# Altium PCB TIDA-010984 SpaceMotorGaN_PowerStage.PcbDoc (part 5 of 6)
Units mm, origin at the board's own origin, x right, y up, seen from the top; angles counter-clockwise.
Board outline 177.8 x 152.4 mm, 8 copper layers (Top Layer, DC LINK Layer 2, GND Layer 3, 3V3 Layer 4, Layer 5, Layer 6, GND Layer 7, Bottom Layer), stack 1.554 mm thick; 582 components, 280 nets, 1847 pads, 979 vias.
Unrouted connection lines stored in the file: 474.
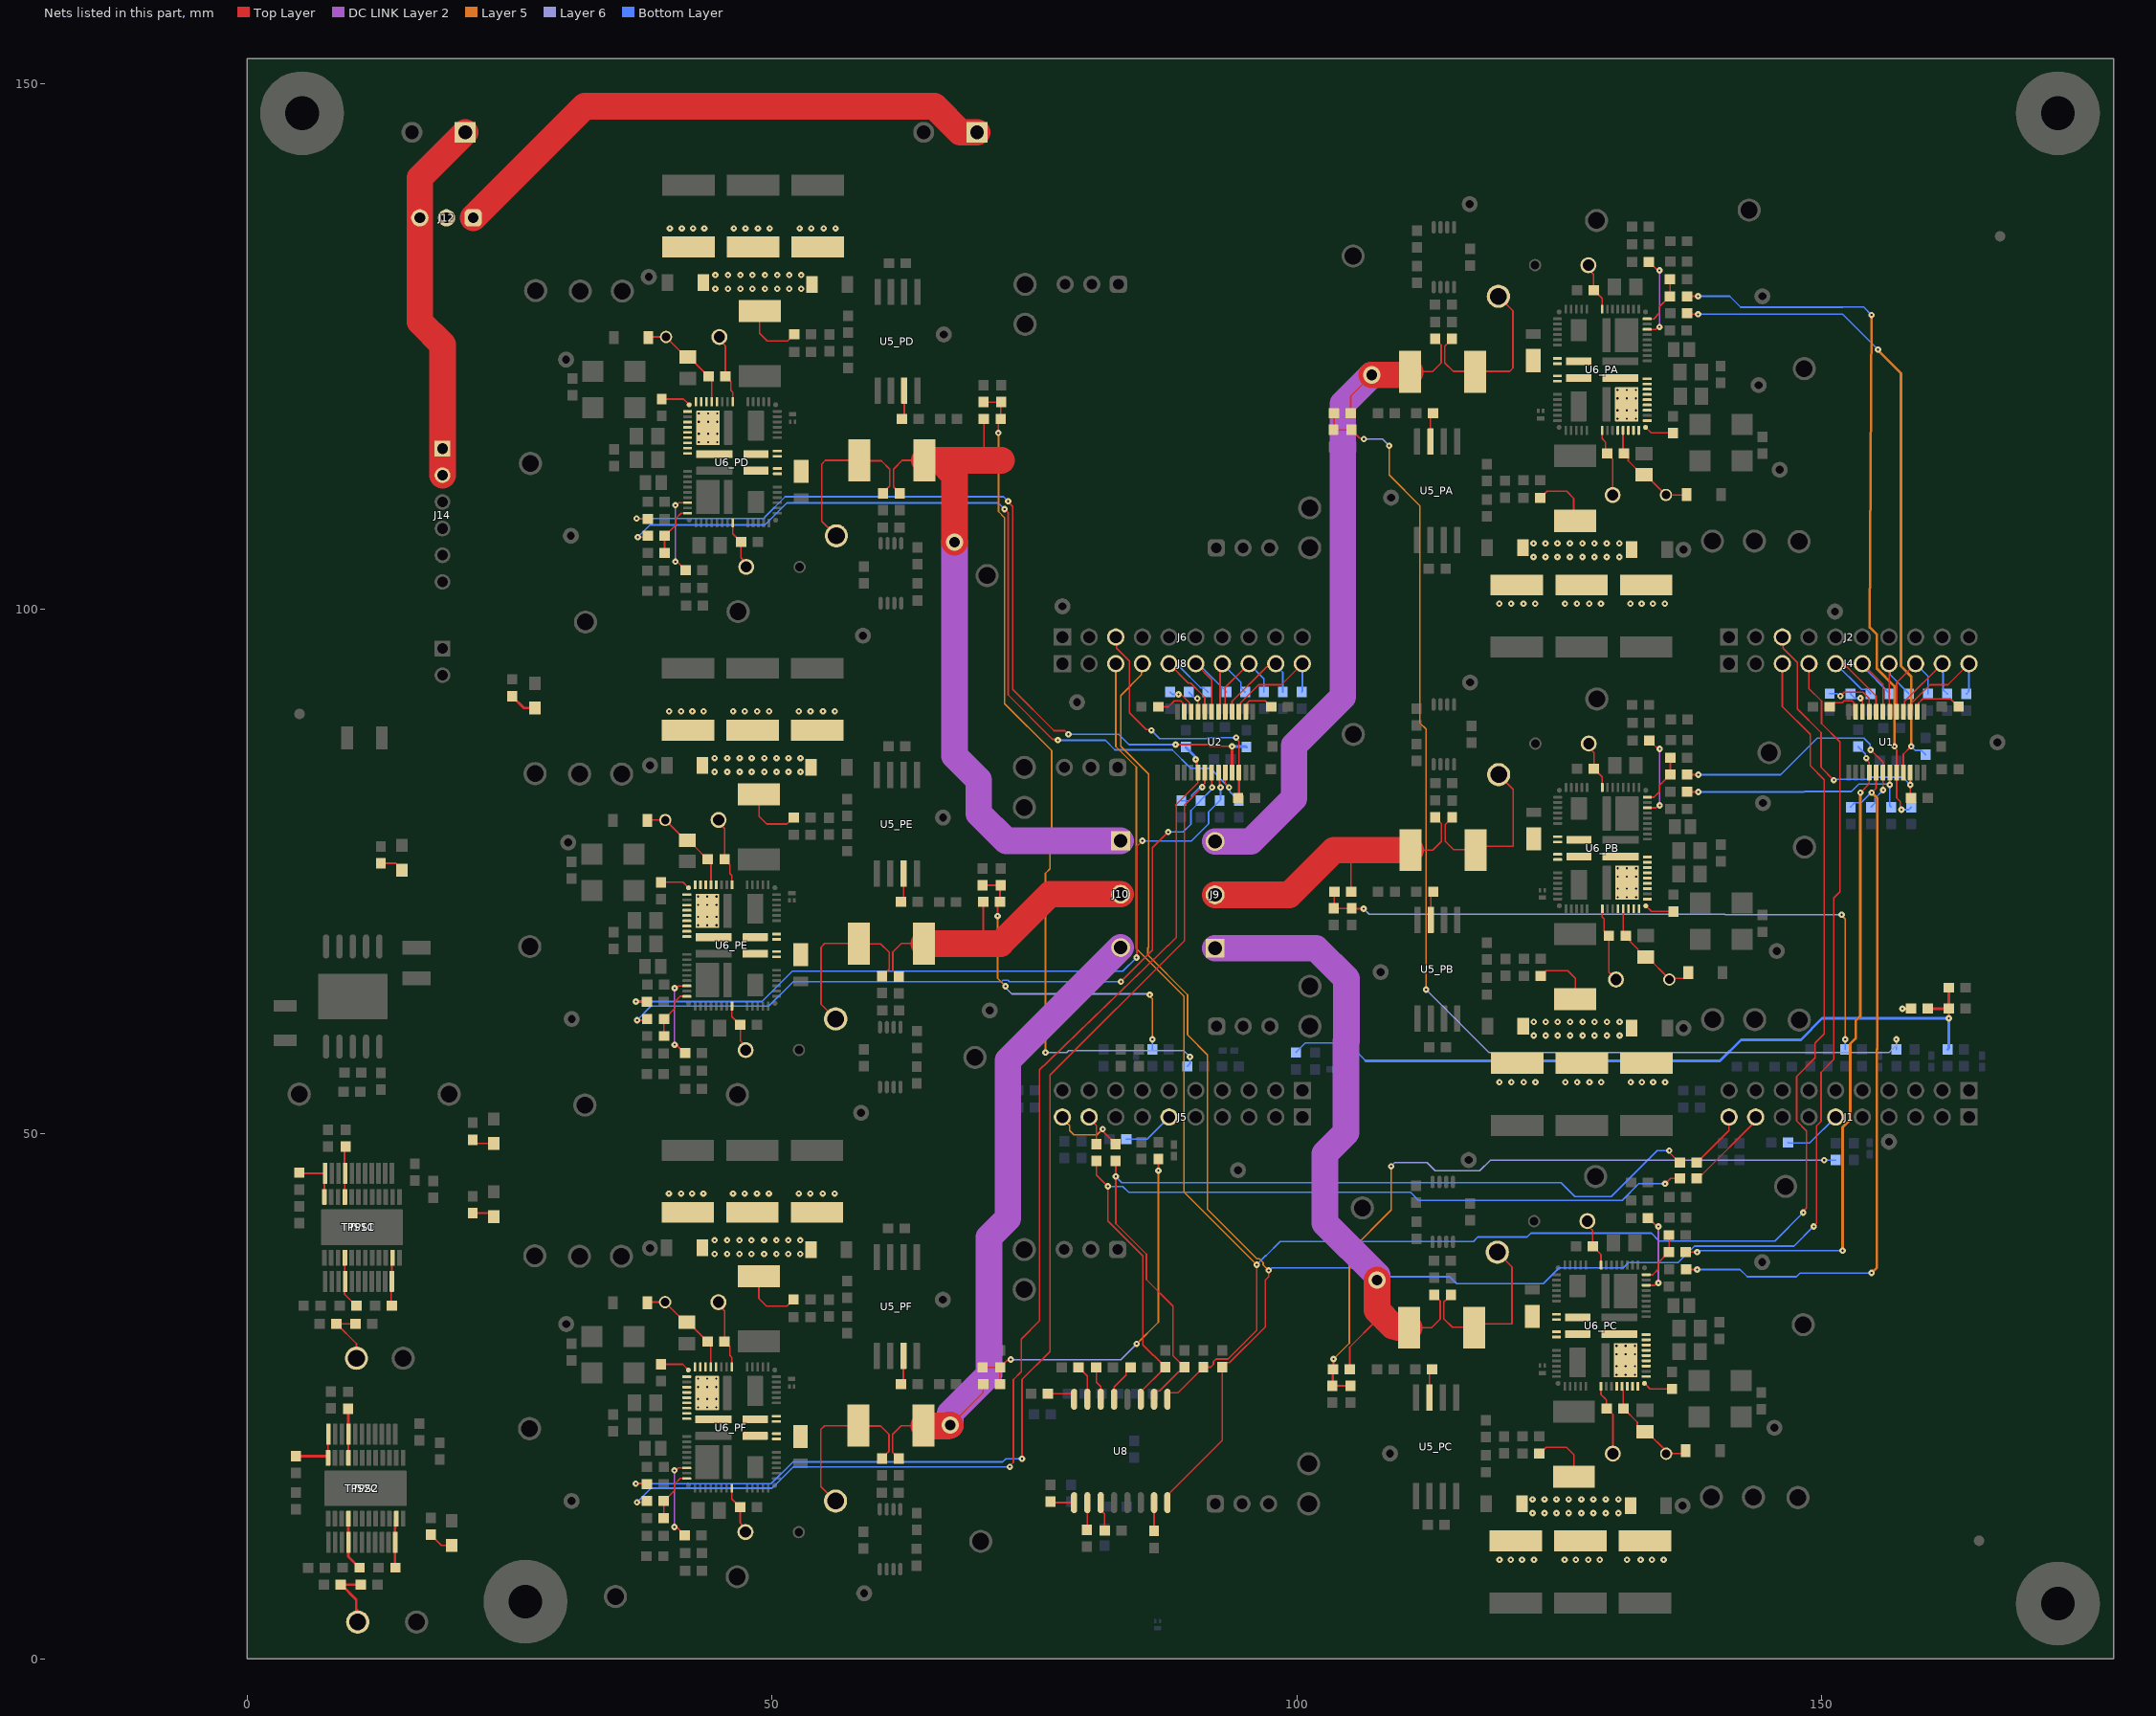
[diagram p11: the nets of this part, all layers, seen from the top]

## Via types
v1: diameter 0.61, hole 0.2, Top Layer to Bottom Layer, tented both sides, 306 vias
v2: diameter 0.61, hole 0.203, Top Layer to Bottom Layer, tented both sides, 272 vias
v3: diameter 0.5, hole 0.2, Top Layer to Bottom Layer, tented both sides, 216 vias
v4: diameter 0.5, hole 0.2, Top Layer to Bottom Layer, 66 vias
v5: diameter 0.61, hole 0.2, Top Layer to Bottom Layer, 61 vias
v6: diameter 0.864, hole 0.406, Top Layer to Bottom Layer, tented both sides, 17 vias
v7: diameter 1.651, hole 1.016, Top Layer to Bottom Layer, tented both sides, 12 vias
v8: diameter 0.864, hole 0.406, Top Layer to Bottom Layer, 9 vias
v9: diameter 0.61, hole 0.203, Top Layer to Bottom Layer, 8 vias
v10: diameter 1.27, hole 0.711, Top Layer to Bottom Layer, tented both sides, 5 vias
v11: diameter 0.61, hole 0.2, Top Layer to Bottom Layer, tented top, 2 vias
v12: diameter 1.651, hole 1.016, Top Layer to Bottom Layer, 2 vias
v13: diameter 0.61, hole 0.203, Top Layer to Bottom Layer, tented bottom, 1 vias
v14: diameter 1.27, hole 0.711, Top Layer to Bottom Layer, 1 vias
v15: diameter 1.651, hole 1.016, Top Layer to Bottom Layer, tented top, 1 vias

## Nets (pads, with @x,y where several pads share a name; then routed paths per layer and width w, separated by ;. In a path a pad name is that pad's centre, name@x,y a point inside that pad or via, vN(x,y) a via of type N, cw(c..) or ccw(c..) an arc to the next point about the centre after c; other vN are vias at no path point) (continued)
NetD10_1: D10.1 R102.1 | length 2.3
  Top Layer w0.152: R102.1@12.75,75.769 14.178,75.769 14.75,75.197 D10.1@14.75,75.122
NetD12_1: D12.1 R110.1 | length 2.6
  Top Layer w0.254: R110.1@25.25,91.675 26.362,90.563 D12.1@27.432,90.563
NetD13_1: D13.1 R111.1 | length 2.1
  Top Layer w0.152: R111.1@21.5,42.45 23.173,42.45 D13.1@23.5,42.123
NetD14_1: D14.1 R112.1 | length 2.4
  Top Layer w0.152: R112.1@17.5,11.84 17.5,11.815 18.511,10.804 D14.1@19.5,10.804
NetD17_1: D17.1 R114.1 | length 2.2
  Top Layer w0.152: R114.1@21.5,49.45 21.875,49.075 D17.1@23.5,49.075
NetJ1_6: J1.6 R14.2 | length 5.6
  Bottom Layer w0.152: R14.2@146.8,49.169 146.849,49.12 148.853,49.12 J1.6@151.336,51.602
NetJ1_9: J1.9 R115.2 | length 8.3
  Top Layer w0.152: R115.2@138.107,45.75 138.506,46.149 138.644,46.149 143.716,51.22 J1.9@143.716,51.602
NetJ1_10: J1.10 R116.2 | length 5.6
  Top Layer w0.152: R116.2@138.096,47.25 138.121,47.25 139.169,48.298 139.169,48.317 141.176,50.323 J1.10@141.176,51.602
NetJ2_3: J2.3 R8.1 U1.22 | length 25.9
  Top Layer w0.152: J2.3@146.256,97.322 146.327,97.252 146.327,96.269 147.695,94.901 147.695,90.474 149.944,88.225 149.944,84.915 v1(151.167,83.692) ; U1.22@158.441,84.416 v1(158.441,83.25) 158.441,82.075 R8.1@158.516,82
  Bottom Layer w0.152: J2.3@146.256,97.322 J2.3@146.327,97.252 ; v1(151.167,83.692) 151.247,83.773 154.438,83.773 154.644,83.979 157.711,83.979 v1(158.441,83.25)
NetJ4_5: J4.5 R19.2 U1.8 | length 11.2
  Top Layer w0.152: J4.5@151.336,94.782 151.606,94.512 152.389,94.512 155.191,91.71 U1.8@155.191,90.216
  Bottom Layer w0.152: J4.5@151.336,94.782 153.785,92.333 154.274,92.333 154.673,91.934 R19.2@154.673,91.909
NetJ4_6: J4.6 R18.2 U1.7 | length 9.3
  Top Layer w0.152: J4.6@153.876,94.782 155.841,92.817 U1.7@155.841,90.216
  Bottom Layer w0.152: J4.6@153.876,94.782 153.876,94.556 156.498,91.934 R18.2@156.498,91.909
NetJ4_7: J4.7 R17.2 U1.6 | length 8.3
  Top Layer w0.152: J4.7@156.416,94.782 156.453,94.745 156.453,90.253 U1.6@156.491,90.216
  Bottom Layer w0.152: J4.7@156.416,94.782 156.528,94.67 156.528,93.729 158.323,91.934 R17.2@158.323,91.909
NetJ4_8: J4.8 R16.2 U1.5 | length 8.7
  Top Layer w0.152: U1.5@157.141,90.216 157.141,92.967 J4.8@158.956,94.782
  Bottom Layer w0.152: J4.8@158.956,94.782 160.148,93.591 R16.2@160.148,91.909
NetJ4_9: J4.9 R15.2 U1.4 | length 9.2
  Top Layer w0.152: U1.4@157.791,90.216 157.908,90.333 157.908,91.194 J4.9@161.496,94.782
  Bottom Layer w0.152: J4.9@161.496,94.782 161.573,94.705 161.573,92.308 R15.2@161.972,91.909
NetJ4_10: J4.10 R13.2 U1.3 | length 10.9
  Top Layer w0.152: U1.3@158.441,90.216 158.589,90.365 158.589,91.051 160.312,92.774 162.027,92.774 J4.10@164.036,94.782
  Bottom Layer w0.152: R13.2@163.797,91.909 164.036,92.148 J4.10@164.036,94.782
NetJ5_6: J5.6 R113.2 | length 5
  Bottom Layer w0.152: R113.2@83.75,49.5 85.733,49.5 J5.6@87.836,51.602
NetJ5_9: J5.9 R117.2 | length 2.9
  Top Layer w0.152: J5.9@80.216,51.602 80.216,51.495 80.907,50.804 R117.2@80.907,49.02
NetJ5_10: J5.10 R118.2 | length 7.1
  Top Layer w0.152: v1(81.517,50.462) 81.517,50.392 81.605,50.304 81.605,50.196 82.756,49.045 R118.2@82.756,49.02
  Layer 5 w0.152: J5.10@77.676,51.602 77.676,51.483 78.361,50.798 78.361,50.318 78.759,49.919 80.974,49.919 v1(81.517,50.462)
NetJ6_3: J6.3 R35.1 U2.22 | length 24.8
  Top Layer w0.152: J6.3@82.756,97.322 82.827,97.252 82.827,96.269 84.049,95.047 84.049,90.12 85.646,88.522 86.066,88.522 v1(86.154,88.435) ; v1(94.227,87.753) 94.227,87.629 94.491,87.365 U2.22@94.491,84.416
  Top Layer w0.254: R35.1@94.491,82.085 U2.22@94.491,84.416
  Bottom Layer w0.152: v1(86.154,88.435) 86.93,87.659 91.431,87.659 91.525,87.753 v1(94.227,87.753)
NetJ8_5: J8.5 R44.2 U2.8 | length 10.9
  Top Layer w0.152: J8.5@87.836,94.782 89.672,92.946 89.893,92.946 91.241,91.598 U2.8@91.241,90.216
  Bottom Layer w0.152: J8.5@87.836,94.782 88.122,94.496 88.832,94.496 90.821,92.508 91.106,92.508 91.505,92.109 R44.2@91.505,92.084
NetJ8_6: J8.6 R43.2 U2.7 | length 9.2
  Top Layer w0.152: J8.6@90.376,94.782 91.891,93.267 U2.7@91.891,90.216
  Bottom Layer w0.152: J8.6@90.376,94.782 90.623,94.782 93.296,92.109 R43.2@93.296,92.084
NetJ8_7: J8.7 R42.2 U2.6 | length 8.3
  Top Layer w0.152: U2.6@92.541,90.216 92.689,90.365 92.689,94.556 J8.7@92.916,94.782
  Bottom Layer w0.152: J8.7@92.916,94.782 94.689,93.009 94.689,92.482 R42.2@95.088,92.084
NetJ8_8: J8.8 R41.2 U2.5 | length 8.8
  Top Layer w0.152: U2.5@93.191,90.216 93.191,92.517 J8.8@95.456,94.782
  Bottom Layer w0.152: J8.8@95.456,94.782 96.88,93.358 R41.2@96.88,92.084
NetJ8_9: J8.9 R40.2 U2.4 | length 9.6
  Top Layer w0.152: U2.4@93.841,90.216 93.841,91.194 97.142,94.496 97.709,94.496 J8.9@97.996,94.782
  Bottom Layer w0.152: J8.9@97.996,94.782 97.996,94.644 98.672,93.968 R40.2@98.672,92.084
NetJ8_10: J8.10 R39.2 U2.3 | length 11.1
  Top Layer w0.152: U2.3@94.491,90.216 94.639,90.365 94.639,91.051 96.362,92.774 98.527,92.774 J8.10@100.536,94.782
  Bottom Layer w0.152: R39.2@100.463,92.084 100.536,92.156 J8.10@100.536,94.782
NetJ11_1: J11.1 J12.1 | length 53.4
  Top Layer w2.54: J12.1@21.54,137.25 32.16,147.87 65.483,147.87 67.953,145.4 J11.1@69.54,145.4
NetR9_1: R9.1 U1.2 | length 5.2
  Top Layer w0.152: U1.2@159.091,90.216 159.239,90.365 159.239,91.051 159.623,91.435 162.274,91.435 163.025,90.683 R9.1@163.05,90.683
NetR26_2: R26.2 U1.11 | length 3.5
  Top Layer w0.152: R26.2@150.768,90.682 151.167,91.081 151.966,91.081 152.127,91.242 152.901,91.242 153.092,91.051 153.092,90.365 U1.11@153.241,90.216
NetR27_2: R27.2 U1.9 | length 5.5
  Top Layer w0.152: v1(151.785,91.712) 151.801,91.712 152.17,92.081 153.934,92.081 154.541,91.474 U1.9@154.541,90.216
  Bottom Layer w0.152: R27.2@150.768,91.933 151.472,91.933 151.693,91.712 v1(151.785,91.712)
NetR28_2: R28.2 U1.10 | length 2.5
  Top Layer w0.152: v1(153.693,91.5) 153.693,91.392 153.891,91.194 U1.10@153.891,90.216
  Bottom Layer w0.152: R28.2@152.765,91.909 152.765,91.899 153.164,91.5 v1(153.693,91.5)
NetR36_1: R36.1 U2.2 | length 3.5
  Top Layer w0.152: U2.2@95.141,90.216 95.289,90.365 95.289,91.051 95.48,91.242 97.004,91.242 97.564,90.682 R36.1@97.589,90.682
NetR51_2: R51.2 U2.11 | length 3.6
  Top Layer w0.152: R51.2@86.8,90.682 87.77,90.682 88.33,91.242 88.951,91.242 89.142,91.051 89.142,90.365 U2.11@89.291,90.216
NetR52_2: R52.2 U2.9 | length 2.4
  Top Layer w0.152: v1(90.535,91.482) 90.563,91.454 90.563,90.244 U2.9@90.591,90.216
  Bottom Layer w0.152: R52.2@89.713,92.084 89.713,92.059 90.202,91.57 90.448,91.57 v1(90.535,91.482)
NetR53_2: R53.2 U2.10 | length 3.2
  Top Layer w0.152: v1(88.733,91.872) 88.821,91.785 89.058,91.785 89.792,91.051 89.792,90.365 U2.10@89.941,90.216
  Bottom Layer w0.152: R53.2@87.921,92.084 88.133,91.872 v1(88.733,91.872)
NetR59_2: R59.2 R61.2 TP2.1 | length 5.9
  Top Layer w0.152: R61.2@8.512,31.892 R61.2@8.537,31.892 ; R59.2@10.332,31.892 R61.2@8.537,31.892 ; TP2.1@10.423,28.624 10.423,30.007 R61.2@8.537,31.892
NetR67_2: R67.2 R69.2 TP4.1 | length 5.9
  Top Layer w0.254: R69.2@8.927,7.069 R69.2@8.952,7.069 ; TP4.1@10.618,3.75 10.618,4.48 10.406,4.693 10.406,5.615 R69.2@8.952,7.069 ; R67.2@10.817,7.069 R69.2@8.952,7.069
NetR79_PA_2: R79_PA.2 U5_PA.3 | length 2.5
  Top Layer w0.152: U5_PA.3@112.739,115.946 R79_PA.2@112.739,118.403
NetR79_PB_2: R79_PB.2 U5_PB.3 | length 2.5
  Top Layer w0.152: U5_PB.3@112.761,70.377 R79_PB.2@112.761,72.834
NetR79_PC_2: R79_PC.2 U5_PC.3 | length 2.5
  Top Layer w0.152: U5_PC.3@112.641,24.89 R79_PC.2@112.641,27.347
NetR79_PD_2: R79_PD.2 U5_PD.3 | length 2.5
  Top Layer w0.152: R79_PD.2@62.609,118.341 U5_PD.3@62.609,120.798
NetR79_PE_2: R79_PE.2 U5_PE.3 | length 2.5
  Top Layer w0.152: R79_PE.2@62.541,72.329 U5_PE.3@62.541,74.786
NetR79_PF_2: R79_PF.2 U5_PF.3 | length 2.5
  Top Layer w0.152: R79_PF.2@62.527,26.405 U5_PF.3@62.527,28.862
NetR81_PA_1: R81_PA.1 U6_PA.17 | length 8
  Top Layer w0.152: U6_PA.17@133.382,126.635 134.202,126.635 134.428,126.861 v1(134.552,126.861) ; R81_PA.1@133.558,133.046 133.583,133.046 134.385,132.244 v1(134.552,132.244)
  DC LINK Layer 2 w0.152: v1(134.552,126.861) v1(134.552,132.244)
NetR81_PB_1: R81_PB.1 U6_PB.17 | length 8
  Top Layer w0.152: U6_PB.17@133.404,81.066 134.224,81.066 134.451,81.292 v1(134.574,81.292) ; R81_PB.1@133.58,87.477 133.605,87.477 134.407,86.675 v1(134.574,86.675)
  DC LINK Layer 2 w0.152: v1(134.574,81.292) v1(134.574,86.675)
NetR81_PC_1: R81_PC.1 U6_PC.17 | length 8
  Top Layer w0.152: U6_PC.17@133.284,35.579 134.104,35.579 134.33,35.805 v1(134.454,35.805) ; R81_PC.1@133.46,41.99 133.485,41.99 134.287,41.188 v1(134.454,41.188)
  DC LINK Layer 2 w0.152: v1(134.454,35.805) v1(134.454,41.188)
NetR81_PD_1: R81_PD.1 U6_PD.17 | length 8
  Top Layer w0.152: v1(40.796,104.5) 40.963,104.5 41.765,103.698 R81_PD.1@41.79,103.698 ; v1(40.796,109.883) 40.92,109.883 41.146,110.109 U6_PD.17@41.966,110.109
  DC LINK Layer 2 w0.152: v1(40.796,104.5) v1(40.796,109.883)
NetR81_PE_1: R81_PE.1 U6_PE.17 | length 8
  Top Layer w0.152: v1(40.728,58.488) 40.895,58.488 41.697,57.686 R81_PE.1@41.722,57.686 ; v1(40.728,63.871) 40.851,63.871 41.078,64.097 U6_PE.17@41.898,64.097
  DC LINK Layer 2 w0.152: v1(40.728,58.488) v1(40.728,63.871)
NetR81_PF_1: R81_PF.1 U6_PF.17 | length 8
  Top Layer w0.152: v1(40.714,12.564) 40.881,12.564 41.683,11.762 R81_PF.1@41.708,11.762 ; v1(40.714,17.947) 40.838,17.947 41.064,18.173 U6_PF.17@41.884,18.173
  DC LINK Layer 2 w0.152: v1(40.714,12.564) v1(40.714,17.947)
NetR93_PA_1: R93_.1@129.558,114.806 TP13_PA.1 U6_PA.57 | length 6.6
  Top Layer w0.152: U6_PA.57@129.083,117.01 129.083,116.22 129.418,115.885 129.418,114.946 R93_.1@129.558,114.806 129.583,114.806 129.982,114.407 129.982,114.382 130.083,114.281 TP13_PA.1@130.083,110.855
NetR93_PB_1: R93_.1@129.731,68.873 TP13_PB.1 U6_PB.57 | length 7.3
  Top Layer w0.152: U6_PB.57@129.105,71.441 129.105,70.651 129.273,70.483 129.273,69.324 129.307,69.289 129.307,69.272 129.706,68.873 R93_.1@129.723,68.873 ; R93_.1@129.731,68.873 129.723,68.865 129.723,65.419 130.406,64.737 TP13_PB.1@130.406,64.7
NetR93_PC_1: R93_.1@129.507,23.848 TP13_PC.1 U6_PC.57 | length 6.9
  Top Layer w0.152: U6_PC.57@128.985,25.954 128.985,25.164 129.32,24.829 129.507,24.642 R93_.1@129.507,23.848 129.532,23.848 130.113,23.267 TP13_PC.1@130.113,19.538
NetR93_PD_1: R93_.1@45.566,122.157 TP13_PD.1 U6_PD.57 | length 6.7
  Top Layer w0.152: TP13_PD.1@44.992,125.907 44.992,125.655 45.566,125.081 R93_.1@45.566,122.157 45.591,122.157 45.99,121.758 45.99,121.733 46.081,121.643 46.081,120.818 46.265,120.633 46.265,120.524 U6_PD.57@46.265,119.734
NetR93_PE_1: R93_.1@45.498,76.145 TP13_PE.1 U6_PE.57 | length 6.7
  Top Layer w0.152: TP13_PE.1@44.924,79.895 44.924,79.643 45.498,79.069 R93_.1@45.498,76.145 45.523,76.145 45.922,75.746 45.922,75.721 46.012,75.631 46.012,74.806 46.197,74.621 46.197,74.512 U6_PE.57@46.197,73.722
NetR93_PF_1: R93_.1@45.484,30.221 TP13_PF.1 U6_PF.57 | length 6.7
  Top Layer w0.152: TP13_PF.1@44.91,33.971 44.91,33.719 45.484,33.144 R93_.1@45.484,30.221 45.509,30.221 45.908,29.822 45.908,29.797 45.999,29.706 45.999,28.881 46.183,28.697 46.183,28.588 U6_PF.57@46.183,27.798
NetR95_PA_2: R95_PA.2 TP14_PA.1 U6_PA.28 | length 4.7
  Top Layer w0.152: TP14_PA.1@127.786,132.744 127.786,132.373 128.287,131.872 R95_PA.2@128.287,130.35 128.312,130.35 129.083,129.579 U6_PA.28@129.083,128.56
NetR95_PB_2: R95_PB.2 TP14_PB.1 U6_PB.28 | length 4.7
  Top Layer w0.152: TP14_PB.1@127.808,87.175 127.808,86.804 128.309,86.303 R95_PB.2@128.309,84.781 128.334,84.781 129.105,84.01 U6_PB.28@129.105,82.991
NetR95_PC_2: R95_PC.2 TP14_PC.1 U6_PC.28 | length 4.7
  Top Layer w0.152: TP14_PC.1@127.688,41.688 127.688,41.317 128.189,40.816 R95_PC.2@128.189,39.294 128.214,39.294 128.985,38.523 U6_PC.28@128.985,37.504
NetR95_PD_2: R95_PD.2 TP14_PD.1 U6_PD.28 | length 4.7
  Top Layer w0.152: U6_PD.28@46.265,108.184 46.265,107.165 47.036,106.394 R95_PD.2@47.061,106.394 47.061,104.872 47.562,104.371 TP14_PD.1@47.562,104
NetR95_PE_2: R95_PE.2 TP14_PE.1 U6_PE.28 | length 4.7
  Top Layer w0.152: U6_PE.28@46.197,62.172 46.197,61.153 46.968,60.382 R95_PE.2@46.993,60.382 46.993,58.86 47.494,58.359 TP14_PE.1@47.494,57.988
NetR95_PF_2: R95_PF.2 TP14_PF.1 U6_PF.28 | length 4.7
  Top Layer w0.152: U6_PF.28@46.183,16.248 46.183,15.229 46.954,14.458 R95_PF.2@46.979,14.458 46.979,12.936 47.48,12.435 TP14_PF.1@47.48,12.064
NetR100_1: R100.1 U8.7 | length 2.7
  Top Layer w0.152: R100.1@86.408,12.171 U8.7@86.408,14.873
NetR101_2: R101.2 U8.13 | length 3.7
  Top Layer w0.152: U8.13@82.598,24.723 82.598,25.89 83.733,27.026 83.733,27.351 84.132,27.75 R101.2@84.157,27.75
NetR103_2: R103.2 U8.3 | length 2.8
  Top Layer w0.152: U8.3@81.328,14.873 81.328,14.17 81.7,13.798 R103.2@81.7,12.221
NetR104_2: R104.2 U8.14 | length 3.2
  Top Layer w0.152: R104.2@80.907,27.75 80.907,26.348 81.328,25.927 U8.14@81.328,24.723
NetR105_2: R105.2 U8.1 | length 2.3
  Top Layer w0.152: R105.2@76.55,14.95 76.627,14.873 U8.1@78.788,14.873
NetR106_2: R106.2 U8.16 | length 2.9
  Top Layer w0.152: R106.2@76.3,25.25 78.581,25.25 78.788,25.043 U8.16@78.788,24.723
NetR107_1: R107.1 U8.2 | length 2.6
  Top Layer w0.152: R107.1@80,12.3 80.058,12.358 U8.2@80.058,14.873
NetR108_2: R108.2 U8.15 | length 3.4
  Top Layer w0.152: R108.2@79.212,27.75 79.237,27.75 80.058,26.929 U8.15@80.058,24.723
PG3: R65.2 TPS2.23 TPS2C.22 | length 4.7
  Top Layer w0.254: R65.2@14.141,8.684 14.086,8.739 14.086,11.095 14.086,12.451 14.119,12.484 14.119,13.242 TPS2.23@14.217,13.34
PG5: R55.2 TPS1.23 TPS1C.22 | length 4.6
  Top Layer w0.152: R55.2@13.792,33.642 13.737,33.697 13.737,35.953 13.802,36.019 13.802,38.133 TPS1.23@13.868,38.198
Phase_PA: J9.3 R85_PA.2 R88_PA.2 R90_PA.1 | length 67.3
  Top Layer w0.152: R88_PA.2@105.148,118.644 105.148,120.297 v7(107.143,122.292) ; R85_PA.2@110.812,122.598 112.937,122.598 113.759,123.419 113.759,125.135 113.18,125.713 R90_PA.1@113.18,125.738 R90_PA.1@113.579,125.339
  Top Layer w2.54: v7(107.143,122.292) 110.592,122.292 110.812,122.512 R85_PA.2@110.812,122.598
  DC LINK Layer 2 w2.54: J9.3@92.216,77.85 95.61,77.85 99.735,81.975 99.735,86.975 104.389,91.629 104.389,119.538 v7(107.143,122.292)
Phase_PB: J9.2 R85_PB.2 R88_PB.2 R90_PB.1 | length 30.2
  Top Layer w0.152: R88_PB.2@105.17,73.075 105.17,76.929 105.27,77.029 ; R85_PB.2@110.834,77.029 112.96,77.029 113.781,77.85 113.781,79.566 113.202,80.144 R90_PB.1@113.202,80.169
  Top Layer w2.54: J9.2@92.216,72.77 99.285,72.77 103.544,77.029 105.27,77.029 R85_PB.2@110.834,77.029
Phase_PC: J9.1 R85_PC.2 R88_PC.2 R90_PC.1 | length 65
  Top Layer w0.152: R88_PC.2@105.05,27.589 105.05,29.688 107.636,32.274 107.636,33.195 ; R85_PC.2@110.714,31.542 112.84,31.542 113.661,32.363 113.661,34.079 113.082,34.657 R90_PC.1@113.082,34.682 R90_PC.1@113.481,34.284
  Top Layer w2.54: v7(107.636,36.079) 107.636,33.195 109.123,31.707 109.5,31.707 109.665,31.542 R85_PC.2@110.714,31.542
  DC LINK Layer 2 w2.54: J9.1@92.216,67.69 101.814,67.69 104.719,64.785 104.719,58.821 ; 104.694,58.796 104.694,50.102 102.693,48.101 102.693,41.496 107.636,36.554 v7(107.636,36.079)
Phase_PD: J10.1 R85_PD.2 R88_PD.2 R90_PD.1 | length 67.5
  Top Layer w0.152: R90_PD.1@61.769,111.404 R90_PD.1@62.168,111.006 62.168,111.031 61.589,111.609 61.589,113.325 62.41,114.146 R85_PD.2@64.536,114.146 ; 70.2,114.146 R88_PD.2@70.2,118.1
  Top Layer w2.54: R85_PD.2@64.536,114.146 70.2,114.146 71.866,114.146 ; 66.014,114.146 67.407,112.754 v12(67.407,106.364)
  DC LINK Layer 2 w2.54: v12(67.407,106.364) 67.407,86.009 69.703,83.713 69.703,80.522 72.317,77.909 J10.1@83.227,77.909
Phase_PE: J10.2 R85_PE.2 R88_PE.2 R90_PE.1 | length 31.1
  Top Layer w0.152: R90_PE.1@61.701,65.393 R90_PE.1@62.1,64.994 62.1,65.019 61.521,65.597 61.521,67.313 62.342,68.134 R85_PE.2@64.468,68.134 ; 70.132,68.134 R88_PE.2@70.132,72.088
  Top Layer w2.54: R85_PE.2@64.468,68.134 70.132,68.134 71.798,68.134 76.493,72.829 J10.2@83.227,72.829
Phase_PF: J10.3 R85_PF.2 R88_PF.2 R90_PF.1 | length 66.4
  Top Layer w0.152: R90_PF.1@61.687,19.468 R90_PF.1@62.086,19.069 62.086,19.094 61.507,19.673 61.507,21.389 62.328,22.21 R85_PF.2@64.454,22.21 ; v12(67,22.25) 70.118,25.368 R88_PF.2@70.118,26.163
  Top Layer w2.54: R85_PF.2@64.454,22.21 64.491,22.174 66.75,22.174 66.826,22.25 v12(67,22.25)
  DC LINK Layer 2 w2.54: v12(67,22.25) 67,23.382 70.693,27.074 70.693,40.15 72.488,41.946 72.488,57.01 J10.3@83.227,67.749
PWM_AH: R20.2 R82_PA.2 U1.21 | length 63.2
  Top Layer w0.152: R82_PA.2@137.173,128.156 137.263,128.066 v1(138.234,128.066) ; U1.21@157.791,84.416 157.791,86.169 v1(158.531,86.909)
  Layer 5 w0.254: v1(155.363,124.708) 155.363,124.637 155.5,124.5 157.568,122.432 157.568,94.541 158.531,93.578 v1(158.531,86.909)
  Bottom Layer w0.152: v1(138.234,128.066) 138.24,128.072 151.999,128.072 v1(155.363,124.708) ; v1(158.531,86.909) 158.533,86.909 158.909,86.533 159.491,86.533 159.889,86.134 R20.2@159.889,86.109
PWM_AL: R21.2 R83_PA.2 U1.20 | length 67.7
  Top Layer w0.152: R83_PA.2@137.164,129.784 v1(138.234,129.784) ; v1(156.936,86.909) 156.936,86.785 157.141,86.581 U1.20@157.141,84.416 157.141,82.009 157.5,81.65 157.5,81.113 157.603,81.01 v1(157.603,80.886)
  Layer 5 w0.254: v1(154.75,128) 154.581,98.246 155.264,97.564 155.264,94.305 156.936,92.633 v1(156.936,86.909)
  Bottom Layer w0.152: v1(138.234,129.784) 141.244,129.784 142.282,128.745 151.994,128.745 151.999,128.75 154,128.75 v1(154.75,128) ; v1(157.603,80.886) 158.308,80.886 R21.2@158.55,81.128
PWM_BH: R22.2 R82_PB.2 U1.19 | length 23
  Top Layer w0.152: R82_PB.2@137.22,82.587 R82_PB.2@137.195,82.587 137.223,82.559 v1(138.256,82.559) ; v1(156.491,83.25) U1.19@156.491,84.416
  Bottom Layer w0.152: v1(138.256,82.559) 148.318,82.559 148.37,82.611 152.831,82.611 153.542,83.322 156.419,83.322 v1(156.491,83.25) 156.491,81.261 R22.2@156.623,81.128
PWM_BL: R23.2 R83_PB.2 U1.18 | length 26.1
  Top Layer w0.152: R83_PB.2@137.186,84.215 v1(138.262,84.215) ; v1(154.663,86.581) 155.841,85.404 U1.18@155.841,84.416 155.851,84.405 155.851,82.751 v1(155.861,82.741)
  Bottom Layer w0.152: v1(138.262,84.215) 146.087,84.215 149.582,87.709 154.036,87.709 154.63,87.115 154.63,86.614 v1(154.663,86.581) ; R23.2@154.696,81.128 155.095,81.527 155.095,81.974 v1(155.861,82.741)
PWM_CH: R24.2 R82_PC.2 U1.17 | length 69
  Top Layer w0.152: R82_PC.2@137.075,37.1 137.091,37.084 v1(138.141,37.084) ; v1(154.768,82.5) 155.191,82.923 U1.17@155.191,84.416
  Layer 5 w0.254: v1(154.75,36.75) 155.264,37.264 155.264,58.042 155.301,58.079 155.301,81.967 v1(154.768,82.5)
  Bottom Layer w0.152: v1(138.141,37.084) 142.234,37.084 142.921,36.397 147.585,36.397 147.938,36.75 v1(154.75,36.75) ; R24.2@152.769,81.128 152.769,81.153 153.168,81.552 153.754,81.552 154.702,82.5 v1(154.768,82.5)
PWM_CL: R25.2 R83_PC.2 U1.16 | length 64.5
  Top Layer w0.152: R83_PC.2@137.066,38.728 v1(138.136,38.728) ; v1(153.693,82.5) 154.541,83.347 U1.16@154.541,84.416 154.541,85.394 154.25,85.685 v1(154.25,85.792)
  Layer 5 w0.254: v1(152,38.882) 152,50.638 152.724,51.361 152.724,58.58 153.242,59.099 153.242,60.77 153.693,61.222 v1(153.693,82.5)
  Bottom Layer w0.152: v1(138.136,38.728) 138.26,38.728 138.414,38.882 v1(152,38.882) ; R25.2@153.471,86.909 153.471,86.884 154.163,86.192 154.163,85.879 v1(154.25,85.792)
PWM_DH: R45.2 R82_PD.2 U2.21 | length 82.7
  Top Layer w0.152: v1(37.114,108.609) 38.154,108.609 R82_PD.2@38.175,108.588 R82_PD.2@38.15,108.588 ; v5(72.5,110.25) 72.5,110.205 72.949,109.756 72.949,92.336 76.884,88.4 77.913,88.4 v1(78.25,88.064) ; v1(88.463,87.078) 88.466,87.081 91.549,87.081 91.721,86.909 v1(93.841,86.909)
  Top Layer w0.254: U2.21@93.841,84.416 v1(93.841,86.909)
  Bottom Layer w0.152: v1(37.114,108.609) 49.251,108.609 49.34,108.699 49.34,108.762 51.271,110.693 72.057,110.693 v5(72.5,110.25) ; v1(78.25,88.064) 83.036,88.064 84.022,87.078 v1(88.463,87.078)
  Bottom Layer w0.254: v1(93.841,86.909) 95.131,86.909 R45.2@95.206,86.835
PWM_DL: R46.2 R83_PD.2 U2.20 | length 83.2
  Top Layer w0.152: v1(37.226,106.843) 38.067,106.843 R83_PD.2@38.184,106.96 ; v5(72.169,109.511) 72.5,109.18 72.5,91.814 76.726,87.587 77.163,87.587 v1(77.25,87.5) ; U2.20@93.191,84.416 93.191,83.395 v1@93.55,83.035
  Bottom Layer w0.152: v1(37.226,106.843) 38.384,108 49.34,108 51.437,110.097 71.583,110.097 v5(72.169,109.511) ; v1(77.25,87.5) 77.267,87.483 81.767,87.483 82.676,86.574 88.145,86.574 89.907,84.812 91.751,84.812 v1@93.55,83.012 ; v1(93.55,83) 93.638,82.913 93.638,82.595 94.473,81.76 R46.2@94.473,81.735
PWM_EH: R47.2 R82_PE.2 U2.19 | length 74.1
  Top Layer w0.152: v1(37.046,62.597) 38.086,62.597 R82_PE.2@38.107,62.576 R82_PE.2@38.082,62.576 ; v1(84.73,66.802) 84.773,66.845 84.773,77.386 v1(85.296,77.909) ; U2.19@92.541,84.416 92.653,84.303 v1@92.653,83.087
  Bottom Layer w0.152: v1(37.046,62.597) 49.058,62.597 51.951,65.49 83.419,65.49 v1(84.73,66.802) ; v1(85.296,77.909) 89.969,77.909 91.604,79.544 91.604,80.663 92.651,81.71 R47.2@92.651,81.735 92.741,81.824 v1(92.741,83)
PWM_EL: R48.2 R83_PE.2 U2.18 | length 73.1
  Top Layer w0.152: v1(37.158,60.831) 37.998,60.831 R83_PE.2@38.116,60.948 ; v1(83.25,64.5) 86.25,67.5 86.25,77.25 v1(87.75,78.75) ; U2.18@91.891,84.416 91.911,84.396 v1@91.911,83.02
  Bottom Layer w0.152: v1(37.158,60.831) 38.482,62.155 49.698,62.155 52.043,64.5 71.866,64.5 72.009,64.643 72.491,64.643 72.634,64.5 v1(83.25,64.5) ; v1(87.75,78.75) 89.157,78.75 89.91,79.504 89.91,80.791 90.83,81.71 R48.2@90.83,81.735 90.83,81.76 91.844,82.774 91.844,82.913 v1(91.931,83)
PWM_FH: R49.2 R82_PF.2 U2.17 | length 114.1
  Top Layer w0.152: v1(37.032,16.673) 38.072,16.673 R82_PF.2@38.093,16.652 R82_PF.2@38.068,16.652 ; v5(73.831,19.052) 73.831,26.605 76.5,29.274 76.5,55.607 89.291,68.397 89.291,81.311 v1(91,83.02) 91,83.144 91.241,83.385 U2.17@91.241,84.416
  Bottom Layer w0.152: v1(37.032,16.673) 49.925,16.673 52.008,18.756 71.994,18.756 72.289,19.052 v5(73.831,19.052) ; R49.2@89.009,81.735 89.712,81.735 89.976,81.999 89.976,82.247 90.662,82.933 90.913,82.933 v1(91,83.02)
PWM_FL: R50.2 R83_PF.2 U2.16 | length 114.6
  Top Layer w0.152: v1(37.144,14.906) 37.985,14.906 R83_PF.2@38.102,15.024 ; v5(72.669,18.29) 72.669,18.382 73,18.713 73,26.587 73.75,27.337 73.75,30.453 75.5,32.203 75.5,56.097 76.3,56.897 88.463,68.647 88.534,68.718 88.534,81.375 ; 88.463,81.305 90.591,83.433 U2.16@90.591,84.416
  Top Layer w0.254: v1(90.376,85.67) 90.444,85.602 90.444,85.321 90.493,85.272 90.493,84.514 U2.16@90.591,84.416
  Bottom Layer w0.152: v1(37.144,14.906) 38.488,16.25 50,16.25 52.04,18.29 v5(72.669,18.29)
  Bottom Layer w0.254: R50.2@89.443,86.835 89.443,86.81 90.308,85.945 90.308,85.738 v1(90.376,85.67)
PWM_LI_PA: C49_PA.1 R83_PA.1 U6_PA.19 | length 5.1
  Top Layer w0.152: U6_PA.19@133.382,127.635 134.006,127.635 134.527,128.156 134.527,128.772 135.539,129.784 R83_PA.1@135.564,129.784 C49_PA.1@135.564,131.411
PWM_LI_PB: C49_PB.1 R83_PB.1 U6_PB.19 | length 5.1
  Top Layer w0.152: U6_PB.19@133.404,82.066 134.028,82.066 134.549,82.587 134.549,83.203 135.561,84.215 R83_PB.1@135.586,84.215 C49_PB.1@135.586,85.843
PWM_LI_PC: C49_PC.1 R83_PC.1 U6_PC.19 | length 5.1
  Top Layer w0.152: U6_PC.19@133.284,36.579 133.908,36.579 134.429,37.1 134.429,37.716 135.441,38.728 R83_PC.1@135.466,38.728 C49_PC.1@135.466,40.356
PWM_LI_PD: C49_PD.1 R83_PD.1 U6_PD.19 | length 5.1
  Top Layer w0.152: C49_PD.1@39.784,105.332 R83_PD.1@39.784,106.96 39.809,106.96 40.821,107.972 40.821,108.588 41.342,109.109 U6_PD.19@41.966,109.109
PWM_LI_PE: C49_PE.1 R83_PE.1 U6_PE.19 | length 5.1
  Top Layer w0.152: C49_PE.1@39.716,59.32 R83_PE.1@39.716,60.948 39.741,60.948 40.753,61.96 40.753,62.576 41.274,63.097 U6_PE.19@41.898,63.097
PWM_LI_PF: C49_PF.1 R83_PF.1 U6_PF.19 | length 5.1
  Top Layer w0.152: C49_PF.1@39.702,13.396 R83_PF.1@39.702,15.024 39.727,15.024 40.739,16.036 40.739,16.652 41.26,17.173 U6_PF.19@41.884,17.173
SCL: R96.1 R115.1 R117.1 U8.11 | length 82.3
  Top Layer w0.152: R117.1@80.907,47.42 80.907,46.093 v5(82,45) 82,41.713 85.331,38.382 85.331,29.909 86.352,28.888 86.389,28.888 87.471,27.806 R96.1@87.471,27.781 87.471,27.756 85.138,25.423 U8.11@85.138,24.723 ; v5(135.083,45.245) 135.114,45.245 135.619,45.75 R115.1@136.507,45.75
  Bottom Layer w0.152: v5(82,45) 83.419,45 83.991,44.428 110.837,44.428 111.596,43.669 115.506,43.669 115.509,43.672 131.003,43.672 132.581,45.25 135.078,45.25 v5(135.083,45.245)
SDA: R97.1 R116.1 R118.1 U8.10 | length 83.8
  Top Layer w0.152: R118.1@82.756,47.42 82.756,41.456 85.683,38.528 85.683,36.127 88.222,33.588 88.222,28.869 89.285,27.806 R97.1@89.285,27.781 89.285,27.756 88.886,27.357 88.768,27.357 86.919,25.509 86.615,25.509 86.408,25.302 U8.10@86.408,24.723 ; v5(135.486,48.406) 135.573,48.319 135.573,48.148 136.471,47.25 R116.1@136.496,47.25
  Bottom Layer w0.152: v5(82.756,45.938) 83.337,45.357 125.166,45.357 126.498,44.024 129.959,44.024 134.341,48.406 v5(135.486,48.406)
SS3: C25.1 TPS2.9 TPS2C.8 | length 4.7
  Top Layer w0.152: TPS2C.8@9.641,21.385 9.654,21.372 9.654,19.153 TPS2.9@9.667,19.14
  Top Layer w0.254: TPS2C.8@9.641,21.385 C25.1@9.641,23.83
SS5: C20.1 TPS1.9 TPS1C.8 | length 4.8
  Top Layer w0.152: TPS1.9@9.318,43.998 9.305,44.011 9.305,46.23 9.292,46.243 9.292,48.676 C20.1@9.402,48.786
STAB3: C26.1 TPS2.12 TPS2C.11 | length 5.4
  Top Layer w0.152: TPS2.12@7.717,19.14 7.726,19.15 7.726,21.376 TPS2C.11@7.736,21.385
  Top Layer w0.254: C26.1@4.648,19.29 7.619,19.29 7.717,19.192 TPS2.12@7.717,19.14
STAB5: C21.1 TPS1.12 TPS1C.11 | length 4.7
  Top Layer w0.152: C21.1@4.997,46.308 5.062,46.243 7.387,46.243 7.377,46.234 7.377,44.008 TPS1.12@7.368,43.998
SW_PA: C47_PA.2 C55_PA.1 D11_PA.2 D15_PA.1 R85_PA.1 R89_PA.1 R93_.2@131.158,114.806 TP10_PA.1 TP13_PA.2 U6_PA.1 U6_PA.2 U6_PA.4 U6_PA.5 U6_PA.6 U6_PA.7 U6_PA.8 U6_PA.9 U6_PA.10 U6_PA.41 U6_PA.42 U6_PA.43 U6_PA.44 U6_PA.60 U6_PA.61 U6_PA.62 U6_PA.63 U6_PA.64 U6_PA.65 U6_PA.66 U6_PA.71 U6_PA.72 | length 30.1
  Top Layer w0.152: R89_PA.1@114.78,125.725 114.78,125.7 114.214,125.135 114.2,125.135 114.111,125.045 114.111,123.441 114.918,122.634 120.283,122.634 120.598,122.949 120.598,128.392 TP10_PA.1@119.206,129.784 ; U6_PA.61@131.083,117.01 131.083,114.881 R93_.2@131.158,114.806 131.183,114.806 131.582,114.407 131.582,114.113 132.918,112.778 C55_PA.1@133.083,112.778 133.248,112.778 TP13_PA.2@135.163,110.863 ; U6_PA.1@133.223,117.294 133.758,116.76 C47_PA.2@135.846,116.76 ; U6_PA.2@133.382,117.935 U6_PA.2@133.682,117.935 ; TP13_PA.2@135.163,110.855 137.102,110.855 D11_PA.2@137.135,110.888
  other v3: 130.557,118.117 131.432,118.117 132.307,118.117 130.557,118.922 131.432,118.922 132.307,118.922 130.557,120.062 131.432,120.062 132.307,120.062 130.557,120.867 131.432,120.867 132.307,120.867
SW_PB: C47_PB.2 C55_PB.1 D11_PB.2 D15_PB.1 R85_PB.1 R89_PB.1 R93_.2@131.331,68.873 TP10_PB.1 TP13_PB.2 U6_PB.1 U6_PB.2 U6_PB.4 U6_PB.5 U6_PB.6 U6_PB.7 U6_PB.8 U6_PB.9 U6_PB.10 U6_PB.41 U6_PB.42 U6_PB.43 U6_PB.44 U6_PB.60 U6_PB.61 U6_PB.62 U6_PB.63 U6_PB.64 U6_PB.65 U6_PB.66 U6_PB.71 U6_PB.72 | length 31
  Top Layer w0.152: R89_PB.1@114.802,80.156 114.802,80.131 114.133,79.462 114.133,77.872 114.94,77.065 116.998,77.065 R85_PB.1@117.034,77.029 117.385,77.38 120.62,77.38 120.62,82.823 TP10_PB.1@119.229,84.215 ; U6_PB.61@131.105,71.441 131.105,69.099 R93_.2@131.331,68.873 131.356,68.873 131.755,68.474 131.755,68.325 132.515,67.565 132.515,67.4 133.074,66.841 C55_PB.1@133.239,66.841 133.404,66.841 TP13_PB.2@135.486,64.76 ; U6_PB.1@133.245,71.725 133.78,71.191 C47_PB.2@135.868,71.191 ; U6_PB.2@133.404,72.366 U6_PB.2@133.704,72.366 ; TP13_PB.2@135.486,64.7 135.596,64.811 136.914,64.811 137.296,65.192 D11_PB.2@137.296,65.344
  other v3: 130.579,72.548 131.454,72.548 132.329,72.548 130.579,73.353 131.454,73.353 132.329,73.353 130.579,74.493 131.454,74.493 132.329,74.493 130.579,75.298 131.454,75.298 132.329,75.298
SW_PC: C47_PC.2 C55_PC.1 D11_PC.2 D15_PC.1 R85_PC.1 R89_PC.1 R93_.2@131.107,23.848 TP10_PC.1 TP13_PC.2 U6_PC.1 U6_PC.2 U6_PC.4 U6_PC.5 U6_PC.6 U6_PC.7 U6_PC.8 U6_PC.9 U6_PC.10 U6_PC.41 U6_PC.42 U6_PC.43 U6_PC.44 U6_PC.60 U6_PC.61 U6_PC.62 U6_PC.63 U6_PC.64 U6_PC.65 U6_PC.66 U6_PC.71 U6_PC.72 | length 30.6
  Top Layer w0.152: R89_PC.1@114.682,34.669 114.682,34.644 114.116,34.079 114.102,34.079 114.013,33.99 114.013,32.385 114.82,31.578 116.877,31.578 R85_PC.1@116.914,31.542 117.265,31.893 120.5,31.893 120.5,37.336 TP10_PC.1@119.109,38.728 ; U6_PC.61@130.92,25.589 U6_PC.61@130.985,25.654 ; U6_PC.61@130.985,25.954 U6_PC.61@130.985,25.654 ; U6_PC.1@133.125,26.238 133.66,25.704 C47_PC.2@135.748,25.704 ; U6_PC.2@133.284,26.879 U6_PC.2@133.584,26.879 ; D11_PC.2@137.004,19.799 D11_PC.2@137.037,19.833 ; D11_PC.2@137.037,19.833 136.742,19.538 TP13_PC.2@135.193,19.538 135.193,19.774 133.337,21.63 C55_PC.1@133.172,21.63 133.007,21.63 132.448,22.188 132.448,22.532 131.132,23.848 R93_.2@131.107,23.848 131.107,25.532 U6_PC.61@130.985,25.654
  other v3: 130.459,27.061 131.334,27.061 132.209,27.061 130.459,27.866 131.334,27.866 132.209,27.866 130.459,29.006 131.334,29.006 132.209,29.006 130.459,29.811 131.334,29.811 132.209,29.811
SW_PD: C47_PD.2 C55_PD.1 D11_PD.2 D15_PD.1 R85_PD.1 R89_PD.1 R93_.2@43.966,122.157 TP10_PD.1 TP13_PD.2 U6_PD.1 U6_PD.2 U6_PD.4 U6_PD.5 U6_PD.6 U6_PD.7 U6_PD.8 U6_PD.9 U6_PD.10 U6_PD.41 U6_PD.42 U6_PD.43 U6_PD.44 U6_PD.60 U6_PD.61 U6_PD.62 U6_PD.63 U6_PD.64 U6_PD.65 U6_PD.66 U6_PD.71 U6_PD.72 | length 30
  Top Layer w0.152: D11_PD.2@38.213,125.855 38.266,125.907 TP13_PD.2@39.912,125.907 39.912,125.9 41.827,123.985 C55_PD.1@41.992,123.985 42.157,123.985 42.716,123.426 42.716,123.382 43.941,122.157 R93_.2@43.966,122.157 44.265,121.858 U6_PD.61@44.265,119.734 ; C47_PD.2@39.502,119.984 41.59,119.984 U6_PD.1@42.125,119.45 ; U6_PD.2@41.666,118.809 U6_PD.2@41.966,118.809 ; TP10_PD.1@56.141,106.96 54.75,108.352 54.75,113.795 55.101,114.146 R85_PD.1@58.336,114.146 58.373,114.11 60.43,114.11 61.237,113.303 61.237,111.699 61.148,111.609 61.134,111.609 60.568,111.044 R89_PD.1@60.568,111.019
  other v3: 43.041,115.877 43.916,115.877 44.791,115.877 43.041,116.682 43.916,116.682 44.791,116.682 43.041,117.822 43.916,117.822 44.791,117.822 43.041,118.627 43.916,118.627 44.791,118.627
SW_PE: C47_PE.2 C55_PE.1 D11_PE.2 D15_PE.1 R85_PE.1 R89_PE.1 R93_.2@43.898,76.145 TP10_PE.1 TP13_PE.2 U6_PE.1 U6_PE.2 U6_PE.4 U6_PE.5 U6_PE.6 U6_PE.7 U6_PE.8 U6_PE.9 U6_PE.10 U6_PE.41 U6_PE.42 U6_PE.43 U6_PE.44 U6_PE.60 U6_PE.61 U6_PE.62 U6_PE.63 U6_PE.64 U6_PE.65 U6_PE.66 U6_PE.71 U6_PE.72 | length 30
  Top Layer w0.152: D11_PE.2@38.145,79.843 38.197,79.895 TP13_PE.2@39.844,79.895 39.844,79.888 41.758,77.973 C55_PE.1@41.924,77.973 42.089,77.973 42.647,77.414 42.647,77.37 43.873,76.145 R93_.2@43.898,76.145 44.197,75.846 U6_PE.61@44.197,73.722 ; C47_PE.2@39.434,73.972 41.522,73.972 U6_PE.1@42.056,73.438 ; U6_PE.2@41.598,72.797 U6_PE.2@41.898,72.797 ; TP10_PE.1@56.073,60.948 54.682,62.34 54.682,67.783 55.033,68.134 R85_PE.1@58.268,68.134 58.304,68.098 60.362,68.098 61.169,67.291 61.169,65.687 61.079,65.597 61.065,65.597 60.5,65.032 R89_PE.1@60.5,65.007
  other v3: 42.973,69.865 43.848,69.865 44.723,69.865 42.973,70.67 43.848,70.67 44.723,70.67 42.973,71.81 43.848,71.81 44.723,71.81 42.973,72.615 43.848,72.615 44.723,72.615
SW_PF: C47_PF.2 C55_PF.1 D11_PF.2 D15_PF.1 R85_PF.1 R89_PF.1 R93_.2@43.884,30.221 TP10_PF.1 TP13_PF.2 U6_PF.1 U6_PF.2 U6_PF.4 U6_PF.5 U6_PF.6 U6_PF.7 U6_PF.8 U6_PF.9 U6_PF.10 U6_PF.41 U6_PF.42 U6_PF.43 U6_PF.44 U6_PF.60 U6_PF.61 U6_PF.62 U6_PF.63 U6_PF.64 U6_PF.65 U6_PF.66 U6_PF.71 U6_PF.72 | length 30
  Top Layer w0.152: D11_PF.2@38.131,33.919 38.183,33.971 TP13_PF.2@39.83,33.971 39.83,33.963 41.745,32.048 C55_PF.1@41.91,32.048 42.075,32.048 42.634,31.49 42.634,31.446 43.859,30.221 R93_.2@43.884,30.221 44.183,29.922 U6_PF.61@44.183,27.798 ; C47_PF.2@39.42,28.048 41.508,28.048 U6_PF.1@42.043,27.513 ; U6_PF.2@41.584,26.873 U6_PF.2@41.884,26.873 ; TP10_PF.1@56.059,15.024 54.668,16.416 54.668,21.859 55.019,22.21 R85_PF.1@58.254,22.21 58.291,22.174 60.348,22.174 61.155,21.367 61.155,19.762 61.066,19.673 61.052,19.673 60.486,19.107 R89_PF.1@60.486,19.082
  other v3: 42.959,23.941 43.834,23.941 44.709,23.941 42.959,24.746 43.834,24.746 44.709,24.746 42.959,25.886 43.834,25.886 44.709,25.886 42.959,26.691 43.834,26.691 44.709,26.691
THERM: J4.4 J8.4 R98.1 U8.8 | length 201.7
  Top Layer w0.152: U8.8@87.678,14.873 87.678,15.573 92.913,20.808 R98.1@92.913,27.781 92.913,27.806 93.312,28.205 93.601,28.205 97,31.604 97,36.079 97.32,36.399 v1(97.32,37) ; J4.4@148.796,94.782 148.796,92.42 149.992,91.224 149.992,89.082 151.748,87.326 151.748,73.052 151.167,72.471 151.167,57.083 149.944,55.86 149.944,51.194 149.5,50.749 149.5,41.5 149.25,41.25 v1(149.25,41.188)
  Layer 5 w0.152: J8.4@85.296,94.782 85.193,94.68 85.193,93.729 83.227,91.762 83.227,86.923 85.877,84.273 85.877,67.766 85.813,67.703 85.813,67.039 89.604,63.248 89.604,59.424 91.5,57.528 91.5,42.82 96.213,38.107 96.431,38.107 96.801,37.738 96.801,37.519 v1(97.32,37)
  Bottom Layer w0.152: v1(97.32,37) 97.381,37 97.631,37.25 108.022,37.25 108.876,36.397 114.555,36.397 115.222,35.729 123.479,35.729 125,37.25 131.105,37.25 131.589,37.734 136.32,37.734 137.895,39.309 147.371,39.309 v1(149.25,41.188)
THERM1: J4.3 J8.3 R99.1 U8.9 | length 192.2
  Top Layer w0.152: U8.9@87.678,24.723 87.678,25.14 87.885,25.347 88.69,25.347 91.099,27.756 R99.1@91.099,27.781 91.802,27.781 92.063,28.041 92.063,28.297 92.323,28.557 93.455,28.557 96.19,31.293 v1(96.19,37.526) ; J4.3@146.256,94.782 146.256,90.71 148.911,88.055 148.911,85.068 150.25,83.729 150.25,59.527 149.377,58.653 149.377,57.237 147.615,55.475 147.615,51.226 148.567,50.274 148.567,43.567 148.567,42.938 148.25,42.621 v1(148.25,42.5)
  Layer 5 w0.152: J8.3@82.756,94.782 82.756,86.896 84.715,84.937 84.715,67.639 89.252,63.102 89.252,44.465 v1(96.19,37.526)
  Bottom Layer w0.152: 97.062,38.409 96.19,37.538 v1(96.19,37.526) 97.068,38.403 98.414,39.75 116.819,39.75 117.25,40.181 121.932,40.181 122.297,40.546 133.779,40.546 134.528,39.797 145.547,39.797 v1(148.25,42.5)
V_PH_PA: C53_PA.1 R4.1 R88_PA.1 R92_PA.2 | length 109.8
  Top Layer w0.152: R88_PA.1@103.548,118.644 103.548,117.098 103.596,117.05 R92_PA.2@105.207,117.05 105.207,117.025 105.97,116.262 106.306,116.262 v1(106.393,116.174)
  Layer 5 w0.152: v1(108.797,115.549) 108.797,112.763 111.736,109.825 111.736,89.136 112.315,88.557 v1(112.314,63.746)
  Layer 6 w0.152: v1(106.393,116.174) 108.172,116.174 v1(108.797,115.549) ; v1(112.314,63.746) 118.31,57.75 156.416,57.75 157.112,58.446 v1(157.112,59)
  Bottom Layer w0.152: R4.1@157.112,58.037 v1(157.112,59)
V_PH_PB: C53_PB.1 R5.1 R88_PB.1 R92_PB.2 | length 63.1
  Top Layer w0.152: R88_PB.1@103.57,73.075 103.57,71.529 103.618,71.481 R92_PB.2@105.229,71.481 105.27,71.441 v1(106.37,71.441)
  Layer 5 w0.152: v1(151.911,70.873) 151.911,70.797 152.25,70.458 v1(152.25,59)
  Layer 6 w0.152: v1(106.37,71.441) 106.882,70.929 140.79,70.929 140.846,70.873 v1(151.911,70.873)
  Bottom Layer w0.152: R5.1@152.242,58.037 152.25,58.046 v1(152.25,59)
V_PH_PC: C53_PC.1 R6.1 R88_PC.1 R92_PC.2 | length 69.6
  Top Layer w0.152: C53_PC.1@103.402,25.994 103.402,27.589 103.5,27.686 v1(103.5,28.557) ; C53_PC.1@103.45,26.042 R88_PC.1@103.45,27.589 ; C53_PC.1@103.498,25.994 R92_PC.2@105.109,25.994
  Layer 5 w0.152: v1(103.5,28.557) 105,30.057 105,38.75 109,42.75 v1(109,46.914)
  Layer 6 w0.152: v1(109,46.914) 109.336,47.25 112.414,47.25 113.189,46.475 117.436,46.475 118.456,47.495 v1(150.25,47.495)
  Bottom Layer w0.152: v1(150.25,47.495) R6.1@151.336,47.495
V_PH_PD: C53_PD.1 R31.1 R88_PD.1 R92_PD.2 | length 80.7
  Top Layer w0.152: R92_PD.2@70.141,119.694 C53_PD.1@71.848,119.694 71.8,119.646 R88_PD.1@71.8,118.1 ; v1(71.568,116.762) R88_PD.1@71.568,117.695
  Layer 5 w0.152: v1(71.568,116.762) 71.588,116.742 71.588,109.27 72.169,108.689 72.169,90.984 76.653,86.5 76.653,77.233 76.5,77.08 76.5,75.25 76.064,74.814 v1(76.064,57.75)
  Layer 6 w0.152: v1(76.064,57.75) 78.091,57.75 78.276,57.935 89.236,57.935 89.421,57.75 v1(89.833,57.338)
  Bottom Layer w0.152: R31.1@89.576,56.436 89.833,56.693 v1(89.833,57.338)
V_PH_PE: C53_PE.1 R32.1 R88_PE.1 R92_PE.2 | length 30.8
  Top Layer w0.152: R92_PE.2@70.073,73.682 C53_PE.1@71.78,73.682 71.732,73.634 R88_PE.1@71.732,72.088 ; v1(71.5,70.75) R88_PE.1@71.5,71.683
  Layer 5 w0.152: v1(71.5,70.75) 71.5,64.812 v1(72.25,64.062) ; v1@85.919,63.331 v1(86,63.25) 86,63.126 86.25,62.876 v1(86.25,59)
  Layer 6 w0.152: v1(72.25,64.062) 72.241,64.054 72.241,63.927 72.837,63.331 v1@85.919,63.331
  Bottom Layer w0.152: v1(86.25,59) 86.25,58.045 R32.1@86.259,58.036
V_PH_PF: C53_PF.1 R33.1 R88_PF.1 R92_PF.2 | length 35.7
  Top Layer w0.152: R92_PF.2@70.059,27.758 C53_PF.1@71.766,27.758 ; R88_PF.1@71.718,26.163 71.718,27.71 C53_PF.1@71.766,27.758 ; v5(72.75,28.5) 72.663,28.413 72.396,28.413 71.766,27.783 C53_PF.1@71.766,27.758 ; v1(86.819,46.5) R33.1@86.819,47.59
  Layer 5 w0.152: v1(84.75,30) 86.819,32.069 v1(86.819,46.5)
  Layer 6 w0.152: v5(72.75,28.5) 83.25,28.5 v1(84.75,30)
VBUS: C35_PA.1 C35_PB.1 C35_PC.1 C35_PD.1 C35_PE.1 C35_PF.1 C36_PA.1 C36_PB.1 C36_PC.1 C36_PD.1 C36_PE.1 C36_PF.1 C38_PA.1 C38_PB.1 C38_PC.1 C38_PD.1 C38_PE.1 C38_PF.1 C39_PA.1 C39_PB.1 C39_PC.1 C39_PD.1 C39_PE.1 C39_PF.1 C40_PA.1 C40_PB.1 C40_PC.1 C40_PD.1 C40_PE.1 C40_PF.1 J12.2 R56.2 R75_PA.1 R75_PB.1 R75_PC.1 R75_PD.1 R75_PE.1 R75_PF.1 R76_PA.2 R76_PB.2 R76_PC.2 R76_PD.2 R76_PE.2 R76_PF.2 | length 36.7
  Top Layer w0.152: R76_PF.2@48.759,36.421 48.759,34.321 49.485,33.594 51.418,33.594 52.038,34.214 R75_PF.1@52.063,34.214 ; R76_PE.2@48.773,82.345 48.773,80.245 49.499,79.519 51.432,79.519 52.051,80.138 R75_PE.1@52.076,80.138 ; R76_PD.2@48.841,128.357 48.841,126.257 49.568,125.531 51.5,125.531 52.12,126.15 R75_PD.1@52.145,126.15 ; R75_PC.1@123.105,19.538 123.401,19.833 123.475,19.833 123.475,19.883 123.75,20.158 125.692,20.158 126.409,19.441 R76_PC.2@126.409,17.331 ; R75_PA.1@123.203,110.594 123.228,110.594 123.848,111.213 125.707,111.213 126.387,110.533 126.387,108.506 R76_PA.2@126.507,108.387 ; R75_PB.1@123.225,65.025 123.25,65.025 123.758,65.532 125.812,65.532 126.529,64.815 R76_PB.2@126.529,62.818 ; v1@157.5,61.926 v1(157.693,61.926) 158.53,61.926 R56.2@158.531,61.928 R56.2@158.516,61.943
  other v2: 119.32,9.438 120.388,9.438 121.453,9.438 122.599,9.438 125.522,9.438 126.591,9.438 127.767,9.438 128.875,9.438 132.763,9.438 133.827,9.438 122.462,13.885 123.597,13.885 124.734,13.885 125.91,13.885 127.116,13.885 128.253,13.885 129.429,13.885 130.634,13.885 122.462,15.188 123.597,15.188 124.734,15.188 125.91,15.188 127.116,15.188 128.253,15.188 129.429,15.188 130.634,15.188 44.534,38.564 45.739,38.564 46.915,38.564 48.052,38.564 49.258,38.564 50.434,38.564 51.571,38.564 52.706,38.564 44.534,39.867 45.739,39.867 46.915,39.867 48.052,39.867 49.258,39.867 50.434,39.867 51.571,39.867 52.706,39.867 40.195,44.314 41.341,44.314 42.405,44.314 43.474,44.314 46.293,44.314 47.401,44.314 48.577,44.314 49.714,44.314 52.56,44.314 53.668,44.314 54.844,44.314 55.981,44.314 119.307,54.925 120.444,54.925 121.62,54.925 122.728,54.925 125.574,54.925 126.711,54.925 127.887,54.925 128.995,54.925 131.814,54.925 132.883,54.925 133.947,54.925 122.582,59.372 123.717,59.372 124.854,59.372 126.03,59.372 127.236,59.372 128.373,59.372 129.549,59.372 130.754,59.372 122.582,60.675 123.717,60.675 124.854,60.675 126.03,60.675 127.236,60.675 128.373,60.675 129.549,60.675 130.754,60.675 44.548,84.488 45.753,84.488 46.929,84.488 48.066,84.488 49.272,84.488 50.448,84.488 51.585,84.488 52.72,84.488 44.548,85.791 45.753,85.791 46.929,85.791 48.066,85.791 49.272,85.791 50.448,85.791 51.585,85.791 52.72,85.791 40.209,90.238 41.355,90.238 42.419,90.238 43.488,90.238 46.307,90.238 47.415,90.238 48.591,90.238 49.728,90.238 52.574,90.238 53.682,90.238 54.858,90.238 55.995,90.238 119.285,100.494 120.422,100.494 121.598,100.494 122.706,100.494 125.552,100.494 126.689,100.494 127.865,100.494 128.973,100.494 131.792,100.494 132.861,100.494 133.925,100.494 135.071,100.494 122.56,104.941 123.695,104.941 124.832,104.941 126.008,104.941 127.214,104.941 128.351,104.941 129.527,104.941 130.732,104.941 122.56,106.244 123.695,106.244 124.832,106.244 126.008,106.244 127.214,106.244 128.351,106.244 129.527,106.244 130.732,106.244 44.616,130.5 45.821,130.5 46.997,130.5 48.134,130.5 49.34,130.5 50.516,130.5 51.653,130.5 52.788,130.5 44.616,131.803 45.821,131.803 46.997,131.803 48.134,131.803 49.34,131.803 50.516,131.803 51.653,131.803 52.788,131.803 40.277,136.25 41.423,136.25 42.487,136.25 43.556,136.25 46.375,136.25 47.483,136.25 48.659,136.25 49.796,136.25 52.642,136.25 53.75,136.25 54.926,136.25 56.063,136.25
  other v9: 131.466,9.438 134.956,9.438 135.083,54.925
VBUS_28V: J12.3 J13.1 J14.1 J14.2 | length 35.4
  Top Layer w2.54: J14.2@18.62,112.735 J14.1@18.62,115.275 18.62,125.182 16.46,127.343 J12.3@16.46,137.25 16.46,141.07 J13.1@20.79,145.4
VDC: C19.1 R3.1 R56.1 R57.2 R72.1 | length 72.9
  Top Layer w0.152: v1(162.112,61) C19.1@162.112,61.926
  Top Layer w0.254: R56.1@160.131,61.928 162.11,61.928 C19.1@162.112,61.926 R57.2@162.112,63.928
  Bottom Layer w0.152: R72.1@99.925,57.749 99.925,57.774 100.813,58.662 104.854,58.662 106.566,56.949
  Bottom Layer w0.254: 106.566,56.949 140.306,56.949 142.325,58.969 148.02,58.969 150.051,61 v1(162.112,61) 162.112,58.137 R3.1@162.013,58.037
VLDO3: C27.1 TPS2.16 TPS2C.15 | length 5.1
  Top Layer w0.254: TPS2.16@9.667,13.34 9.654,13.327 9.654,11.108 9.641,11.095 9.641,9.739 10.696,8.684 C27.1@10.721,8.684
VLDO5: C22.1 TPS1.16 TPS1C.15 | length 5
  Top Layer w0.152: TPS1.16@9.318,38.198 9.305,38.185 9.305,35.966 9.292,35.953 9.292,34.734 10.383,33.642 C22.1@10.408,33.642
pads on no net: FID1.1 FID2.1 FID3.1 H1.1 H2.1 H3.1 H4.1 J1.1 J1.2 J1.3 J1.4 J1.5 J1.7 J1.8 J2.1 J2.2 J2.4 J2.5 J2.6 J2.7 J2.8 J2.9 J3.1 J4.1 J4.2 J5.1 J5.2 J5.3 J5.4 J5.5 J5.7 J5.8 J6.1 J6.2 J6.4 J6.5 J6.6 J6.7 J6.8 J6.9 J7.1 J8.1 J8.2 LBL1.0 U1.14 U1.15 U2.14 U2.15 U4.5
copper on no net: | length 1
  Top Layer w0.152: 49.499,55.687 49.572,55.687 50.25,55.009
